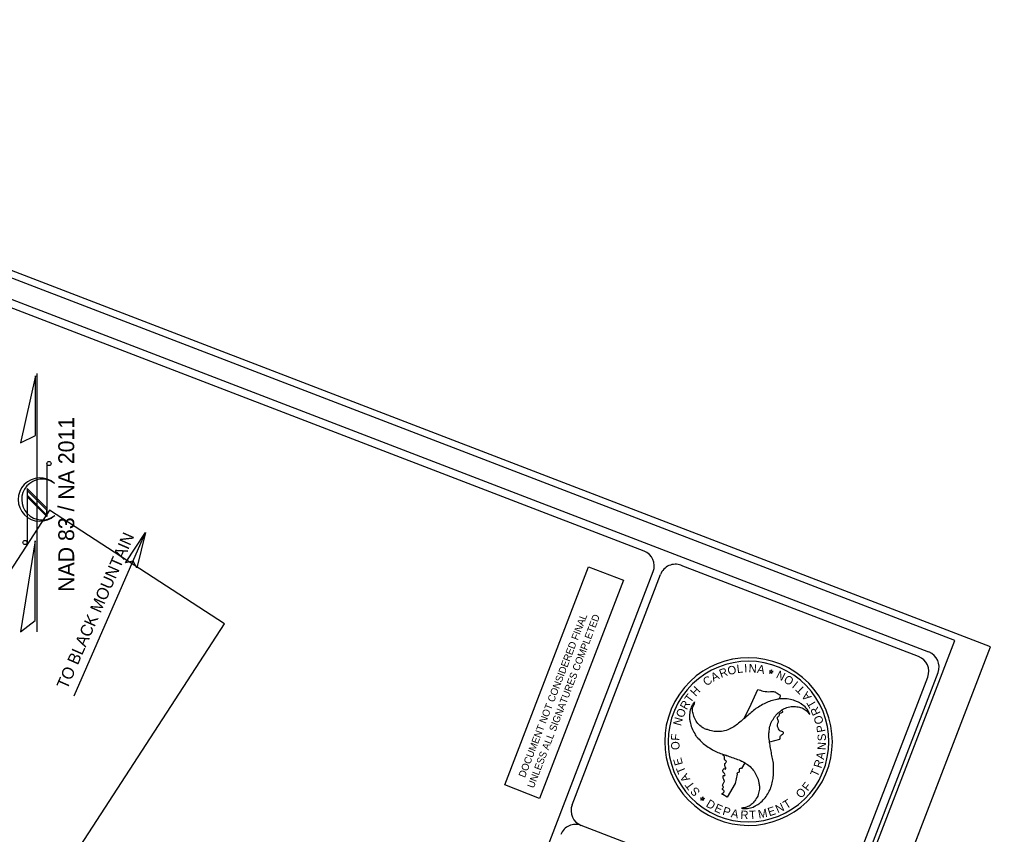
# Model space of a CAD drawing. Extents: x 1015221 to 1064345, y 619216 to 647967.
# Drawn here: x 1023380 to 1028267, y 643866 to 647967 of the extents above; entities that cross this region are included whole.
import ezdxf

# ---------------------------------------------------------------- set-up
doc = ezdxf.new("R2010")
doc.units = 0
for name, color, linetype in [('Prop DSN Text', 7, 'Continuous'), ('Prop Terminator CELL', 7, 'Continuous'), ('Scratch_Level_2', 7, 'Continuous'), ('Sheet Cutting Line CELL', 7, 'Continuous'), ('Sheet North Arrow CELL', 7, 'Continuous'), ('Sheet Plot Border Inside CELL', 7, 'Continuous'), ('Sheet Plot Border Outside CELL', 7, 'Continuous'), ('Sheet Sticker Exception Certification CELL', 7, 'Continuous'), ('Sheet Title CELL', 7, 'Continuous')]:
    doc.layers.add(name, color=color, linetype=linetype)

msp = doc.modelspace()

# ---------------------------------------------------------------- linework, layer by layer
at = {"layer": 'Prop DSN Text'}
msp.add_line((1023655.6, 644563.8), (1024014.9, 645385.8), dxfattribs=at)
at = {"layer": 'Prop Terminator CELL'}
msp.add_lwpolyline([(1023914.4, 645233.3), (1024014.9, 645385.8), (1023971.8, 645207.2), (1023951.7, 645241)], close=True, dxfattribs=at)
at = {"layer": 'Scratch_Level_2'}
msp.add_lwpolyline([(1020895.4, 635853.8), (1022473.8, 638805.7), (1023379.2, 639473.6), (1023843, 640900.1), (1023637.3, 641036.3), (1023148.3, 642068.8), (1023188.2, 643043.1), (1024411.5, 644926.1), (1023531, 645498.1), (1022160.6, 643388.7), (1022151.2, 643382.8), (1022046.3, 641942.6), (1021939, 640556.9), (1021513.5, 639679.1), (1020439.2, 638632.2), (1020121.4, 637513.2), (1020059.5, 637223.8), (1019861.3, 636035.8)], close=True, dxfattribs=at)
at = {"layer": 'Sheet Cutting Line CELL'}
msp.add_line((1023435, 632235.3), (1028266.7, 644811.1), dxfattribs=at)
at = {"layer": 'Sheet North Arrow CELL'}
for p, q in [((1023469.5, 644885.3), (1023469.5, 646185.3)), ((1023518.5, 645732.9), (1023518.5, 645466.1)), ((1023518.5, 645507.7), (1023419.1, 645607.1)), ((1023419.1, 645607.1), (1023419.1, 645335.9)), ((1023555.3, 645633.5), (1023556.7, 645632.5)), ((1023518.5, 645497.9), (1023419.1, 645597.3)), ((1023419.1, 645597.3), (1023419.1, 645572.9)), ((1023518.5, 645473.5), (1023419.1, 645572.9)), ((1023419.1, 645572.9), (1023518.5, 645473.5)), ((1023518.5, 645466.1), (1023419.1, 645565.5)), ((1023518.5, 645473.5), (1023518.5, 645497.9))]:
    msp.add_line(p, q, dxfattribs=at)
for points in [[(1023460.5, 646173.9), (1023386.3, 645836.3), (1023460.5, 645873.9)], [(1023458.9, 645343.3), (1023385.3, 644885.3), (1023458.9, 644943.3)]]:
    msp.add_lwpolyline(points, close=True, dxfattribs=at)
for centre in [(1023529.1, 645732.7), (1023408.5, 645335.5)]:
    msp.add_circle(centre, 10.6, dxfattribs=at)
for centre, radius, start, end in [((1023483.4, 645551.5), 109.2, 47.84, 312.3941), ((1023493.9, 645551.6), 102.4, 53.095, 308.6287)]:
    msp.add_arc(centre, radius, start, end, dxfattribs=at)
at = {"layer": 'Sheet Plot Border Inside CELL'}
msp.add_lwpolyline([(1023304.8, 632396.8), (1028086.2, 644841.8), (1020206.9, 647869.1), (1015425.5, 635424)], close=True, dxfattribs=at)
at = {"layer": 'Sheet Plot Border Outside CELL'}
msp.add_lwpolyline([(1020052.2, 647967.1), (1015220.5, 635391.3), (1023435, 632235.3), (1028266.7, 644811.1)], close=True, dxfattribs=at)
at = {"layer": 'Sheet Sticker Exception Certification CELL'}
for p, q in [((1025821.9, 644115.6), (1026243.7, 645213.4)), ((1026243.8, 645213.3), (1026419.3, 645145.9)), ((1026419.2, 645145.9), (1025997.4, 644048.2)), ((1025997.4, 644048.2), (1025821.9, 644115.6))]:
    msp.add_line(p, q, dxfattribs=at)
at = {"layer": 'Sheet Title CELL'}
for p, q in [((1022495.1, 634584.7), (1026569.3, 645189)), ((1026161.2, 644015.4), (1026606.6, 645174.6)), ((1027160.8, 644688.8), (1027153.7, 644689.8)), ((1027153.7, 644689.8), (1027158.5, 644684.6)), ((1027158.5, 644684.6), (1027155.1, 644678.3)), ((1027155.1, 644678.3), (1027161.7, 644681.5)), ((1027164, 644695.2), (1027160.8, 644688.8)), ((1027161.7, 644681.5), (1027166.8, 644676.3)), ((1027165.1, 644687.9), (1027164, 644695.2)), ((1027172.3, 644686.4), (1027165.1, 644687.9)), ((1027165.8, 644683.3), (1027172.3, 644686.4)), ((1027166.8, 644676.3), (1027165.8, 644683.3)), ((1027250.4, 644704.3), (1027250.4, 644704.3)), ((1026776.7, 644533.2), (1026777.1, 644532.1)), ((1026776.7, 644533.2), (1026777.1, 644532.1)), ((1027025.7, 644448.8), (1027025.7, 644448.8)), ((1027205.3, 644344.1), (1027154.6, 644331.4)), ((1027154.6, 644331.4), (1027154.6, 644331.4)), ((1027030.1, 644227.2), (1027013.8, 644198.1)), ((1026992.3, 644169.6), (1026982.2, 644122.9)), ((1026982.2, 644122.9), (1026941.2, 644054.1)), ((1026812.9, 644045.6), (1026807.9, 644050.6)), ((1026807.9, 644050.6), (1026815.1, 644049.6)), ((1026809.4, 644039.1), (1026812.9, 644045.6)), ((1026816, 644042.2), (1026809.4, 644039.1)), ((1026815.1, 644049.6), (1026818.5, 644055.9)), ((1026821.2, 644037), (1026816, 644042.2)), ((1026818.5, 644055.9), (1026819.5, 644048.6)), ((1026819.5, 644048.6), (1026826.7, 644047.2)), ((1026826.7, 644047.2), (1026820, 644044)), ((1026820, 644044), (1026821.2, 644037)), ((1026941.2, 644054.1), (1026919.4, 644067)), ((1027402.1, 643453), (1026207.2, 643912))]:
    msp.add_line(p, q, dxfattribs=at)
for points in [[(1027956.5, 644784.5), (1020264.8, 647739.7)], [(1026523.4, 645292.3), (1020287.7, 647688.1)], [(1027904.8, 644761.5), (1026710, 645220.6)], [(1023756.2, 633628.8), (1028002.6, 644681.1)], [(1027505.5, 643499), (1027950.8, 644658.2)]]:
    msp.add_lwpolyline(points, dxfattribs=at)
for centre, radius, start, end in [((1026494.3, 645217.8), 80, 338.983, 68.983), ((1026681, 645146.1), 80, 68.983, 158.983), ((1027927.5, 644710), 80, 338.983, 68.983), ((1027048.7, 644334), 421.7, 61.4042, 241.4042), ((1027048.7, 644334), 404.2, 61.4042, 241.4042), ((1027875.8, 644687), 80, 338.983, 68.983), ((1027048.7, 644334), 421.7, 241.4042, 61.4042), ((1027048.7, 644334), 404.2, 241.4042, 61.4042), ((1025053, 645474.8), 2223.6, 332.5217, 336.7277), ((1025053, 645474.8), 2223.6, 327.0826, 327.1822), ((1026235.9, 643986.7), 80, 158.983, 248.983), ((1026178.5, 643837.4), 80, 68.983, 158.983)]:
    msp.add_arc(centre, radius, start, end, dxfattribs=at)
for points in [[(1027095.7, 644596.2), (1027123.2, 644588), (1027159.4, 644585.1), (1027179.8, 644584.8), (1027193.4, 644577.1), (1027208.1, 644565), (1027201.1, 644548.3)], [(1026777.1, 644532.1), (1026770.4, 644524.9), (1026758, 644499.8), (1026752.3, 644470.4), (1026752.3, 644467.6), (1026752.1, 644451.5), (1026754.8, 644432.8), (1026762.8, 644402.4), (1026777.8, 644374.3), (1026784.4, 644362.7), (1026794.3, 644351.5), (1026815.9, 644329), (1026838.8, 644311), (1026867.4, 644293.2), (1026893.6, 644279.5), (1026922.4, 644269.4), (1026951.5, 644259.5), (1026979.5, 644249.2), (1027008.2, 644238.3), (1027034.7, 644224), (1027036.9, 644222.6), (1027062.6, 644202.5), (1027081, 644177.6), (1027093.8, 644151.6), (1027098.6, 644137.7), (1027101.5, 644120.1), (1027103.3, 644110), (1027102.7, 644088.5), (1027094.8, 644060), (1027079.8, 644035.9), (1027062.3, 644017), (1027039.3, 644004.5), (1027013.2, 643998.9)], [(1027356.9, 644470.3), (1027354.1, 644479.2), (1027338.6, 644502.8), (1027316, 644522.4), (1027313.6, 644524.1), (1027299.6, 644532), (1027282, 644539.2), (1027251.7, 644547.7), (1027219.9, 644548.4), (1027206.6, 644548.7), (1027191.7, 644545.7), (1027161.6, 644538.2), (1027134.5, 644527.5), (1027105, 644511.4), (1027080.2, 644495.4), (1027056.6, 644475.7), (1027033.6, 644455.5), (1027010.9, 644436.5), (1026986.8, 644416.8), (1026961.3, 644401.2), (1026958.9, 644400.1), (1026928.5, 644387.7), (1026897.7, 644384.2), (1026868.9, 644386), (1026854.8, 644389.1), (1026837.9, 644395.5), (1026828, 644398.7), (1026810.1, 644410.2), (1026789, 644431.4), (1026775.8, 644456.1), (1026768.4, 644480.8), (1026769, 644507), (1026777.1, 644532.1), (1026776.7, 644533.2)], [(1027201.1, 644548.1), (1027191.7, 644545.7), (1027161.6, 644538.2), (1027134.5, 644527.5), (1027105, 644511.4), (1027080.2, 644495.4), (1027056.6, 644475.7), (1027033.6, 644455.5), (1027025.7, 644448.8)], [(1027013.2, 643998.9), (1027023, 643997), (1027051, 643998.7), (1027079.3, 644008.3), (1027081.5, 644009.8), (1027096, 644017.7), (1027110.6, 644029.4), (1027133.2, 644051.5), (1027149.6, 644078.5), (1027156.5, 644089.9), (1027161.5, 644104.7), (1027169.8, 644134.1), (1027174.2, 644162.7), (1027175.1, 644196.7), (1027173.8, 644225.9), (1027168.3, 644256.2), (1027162.1, 644286.3), (1027157.2, 644315.8), (1027152.5, 644346.1), (1027151.4, 644376.2), (1027151.8, 644379.2), (1027156.3, 644411.5), (1027168.5, 644439.6), (1027184.3, 644463.4), (1027194.2, 644475), (1027208.2, 644485.8), (1027216, 644493), (1027234.8, 644502.8), (1027263.4, 644510.1), (1027291.5, 644509.4), (1027316.9, 644503.5), (1027339.2, 644489.9), (1027356.9, 644470.3)], [(1027154.6, 644331.4), (1027152.5, 644346.1), (1027151.4, 644376.2), (1027151.8, 644379.2), (1027156.3, 644411.5), (1027168.5, 644439.6), (1027184.3, 644463.4), (1027194.2, 644475), (1027208.2, 644485.8), (1027215.5, 644492.4)], [(1027215.5, 644492.3), (1027220.2, 644485.3), (1027217.6, 644479.5), (1027204.4, 644474), (1027200.3, 644460.7), (1027194.2, 644456.9), (1027192.1, 644453.4), (1027198.2, 644438.8), (1027194.4, 644425.5), (1027198.1, 644398.6), (1027204.1, 644390.1), (1027222.7, 644381.9), (1027223.6, 644375.2), (1027219.7, 644370), (1027208.6, 644360.7), (1027205.3, 644344.1)], [(1026919.4, 644067), (1026916.9, 644067.4), (1026916.5, 644072.4), (1026926.5, 644080.5), (1026924.8, 644088.2), (1026920.2, 644090.5), (1026918, 644097.1), (1026923.3, 644103.5), (1026918.6, 644114.4), (1026920.4, 644121.1), (1026927.2, 644133.6), (1026920.4, 644156.6), (1026922.9, 644163.3), (1026927.7, 644162.7), (1026930.6, 644166.1), (1026921.7, 644179.2), (1026920.9, 644181.8), (1026922.6, 644195.9), (1026926.5, 644197.8), (1026932.4, 644195.7), (1026934.4, 644196.8), (1026933.8, 644202.1), (1026930, 644210.8), (1026930.3, 644223.1), (1026937.5, 644233.2), (1026929.7, 644239.9), (1026928, 644257.3), (1026924.3, 644262.8), (1026919.4, 644266.3)], [(1026921.6, 644269.6), (1026922.4, 644269.4), (1026951.5, 644259.5), (1026979.5, 644249.2), (1027008.2, 644238.3), (1027030, 644227.1)], [(1027013.8, 644198.1), (1027006.8, 644198.2), (1027002.1, 644193.4), (1027001.9, 644183.5), (1026998.4, 644177.8), (1026990.4, 644174), (1026992.3, 644169.6)]]:
    msp.add_spline(points, degree=3, dxfattribs=at)

# ---------------------------------------------------------------- texts
at = {"layer": 'Prop DSN Text'}
msp.add_text('TO BLACK MOUNTAIN', height=60, rotation=66.3868, dxfattribs=at).set_placement((1023620.2, 644592.9))
at = {"layer": 'Sheet North Arrow CELL'}
msp.add_text('NAD 83 / NA 2011', height=80, rotation=90, dxfattribs=at).set_placement((1023655.8, 645087.4))
at = {"layer": 'Sheet Sticker Exception Certification CELL'}
for s, p in [('DOCUMENT NOT CONSIDERED FINAL', (1025923.7, 644149.7)), ('UNLESS ALL SIGNATURES COMPLETED', (1025967.9, 644096.6))]:
    msp.add_text(s, height=36, rotation=68.983, dxfattribs=at).set_placement(p)
at = {"layer": 'Sheet Title CELL'}
for s, height, rotation, p in [('L', 41.9, 6.9889, (1026991.8, 644678.1)), ('I', 42.1, 2.9996, (1027028, 644681.8)), ('N', 42, 357.2995, (1027048.5, 644682.5)), ('A', 42, 26.7062, (1026872, 644634.5)), ('R', 42, 20.3422, (1026910.5, 644654)), ('O', 42.1, 13.2226, (1026948.2, 644667.9)), ('A', 42.1, 349.8675, (1027089.7, 644680.3)), ('N', 42.1, 153.6123, (1027238.8, 644675.7)), ('C', 41.9, 34.2032, (1026837.1, 644611.1)), ('O', 41.9, 146.3643, (1027281.4, 644648)), ('I', 42.2, 141.2286, (1027302.6, 644631.3)), ('T', 42.2, 53.6303, (1026757.4, 644525.6)), ('H', 42, 46.5455, (1026782, 644558.6)), ('T', 42, 135.5787, (1027336.7, 644598.2)), ('A', 42.1, 128.4943, (1027368.1, 644559.6)), ('R', 42.1, 60.2799, (1026737.4, 644490.6)), ('T', 41.9, 120.4073, (1027392.9, 644518.9)), ('O', 42.2, 66.8898, (1026720, 644449.8)), ('R', 42.1, 114.3075, (1027412.6, 644476.7)), ('N', 42.1, 74.3879, (1026708.7, 644410.2)), ('O', 42.1, 107.1184, (1027427.9, 644428.2)), ('P', 42, 100.4264, (1027436.4, 644384)), ('O', 42.1, 93.6217, (1026702.8, 644293.1)), ('F', 42.1, 86.4749, (1026700.2, 644337.5)), ('S', 41.9, 93.2345, (1027439.3, 644337.5)), ('N', 41.9, 86.0241, (1027436.9, 644290)), ('E', 41.9, 105.5611, (1026719.3, 644220.4)), ('R', 42.1, 72.2393, (1027414.6, 644196.7)), ('A', 41.9, 78.9924, (1027428.1, 644241.1)), ('T', 42, 112.6767, (1026735, 644182.3)), ('T', 41.9, 65.2827, (1027395.2, 644153.2)), ('A', 42.2, 119.7319, (1026756.5, 644144.6)), ('T', 42.1, 126.7842, (1026780.7, 644111.3)), ('S', 42, 133.1604, (1026808, 644082)), ('O', 42, 45.2082, (1027311.8, 644045.3)), ('F', 42, 52.3734, (1027347.2, 644081.8)), ('D', 42.1, 329.2572, (1026831.1, 644009.6)), ('T', 42, 31.9045, (1027239, 643992.9)), ('E', 41.9, 335.545, (1026872.9, 643985.3)), ('P', 42.1, 343.0774, (1026914.8, 643967.2)), ('A', 42, 349.67, (1026957.8, 643954.1)), ('R', 42, 356.7386, (1027006.9, 643945.7)), ('T', 42, 3.3892, (1027053.2, 643943.5)), ('M', 41.9, 10.6242, (1027100.8, 643947)), ('E', 41.9, 18.091, (1027153.2, 643957.8)), ('N', 42.1, 25.0625, (1027196.2, 643972.3))]:
    msp.add_text(s, height=height, rotation=rotation, dxfattribs=at).set_placement(p)

doc.saveas('drawing.dxf')
